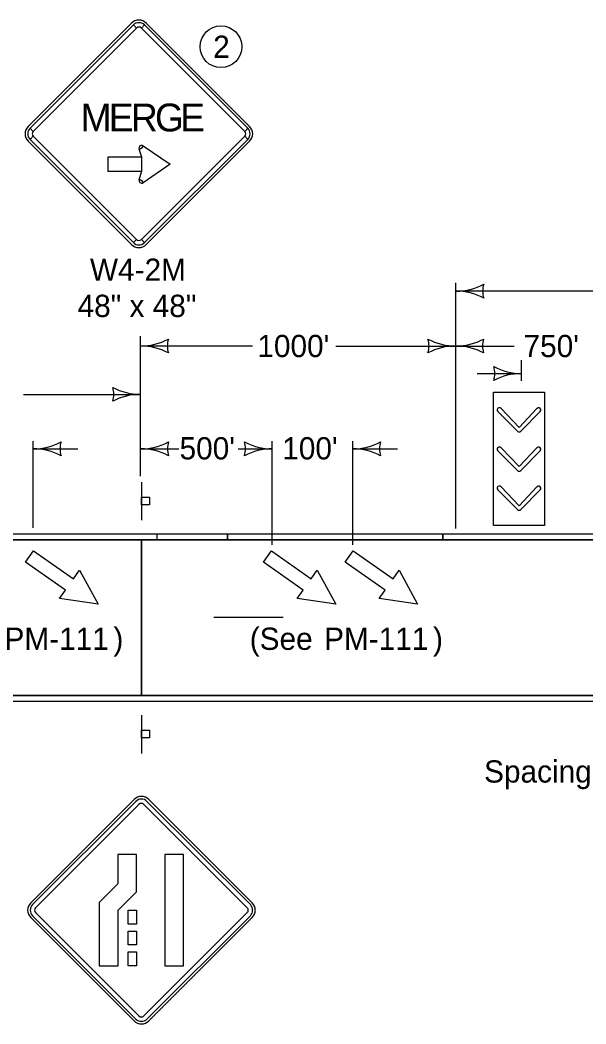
# Model space of a CAD drawing. Extents: x 10134 to 13311, y 7934 to 9733.
# Drawn here: x 10902 to 11309, y 9011 to 9733 of the extents above; entities that cross this region are included whole.
import ezdxf

# ---------------------------------------------------------------- set-up
doc = ezdxf.new("R2010")
doc.units = 0
for name, color, linetype in [('dsnCellElements', 7, 'Continuous'), ('dsnstdModifiedBlock', 7, 'Continuous'), ('dsnStdNote', 7, 'Continuous'), ('dsnStdShading', 7, 'Continuous'), ('SheetText', 7, 'Continuous')]:
    doc.layers.add(name, color=color, linetype=linetype)

msp = doc.modelspace()

# ---------------------------------------------------------------- linework, layer by layer
at = {"layer": 'dsnCellElements'}
for p, q in [((10982.3, 9730.38), (10908.06, 9656.13)), ((10983.63, 9729.05), (10985.84, 9726.84)), ((10989.37, 9726.84), (10991.58, 9729.05)), ((11067.15, 9656.13), (10992.91, 9730.38)), ((10911.59, 9652.59), (10909.38, 9654.8)), ((11065.83, 9654.8), (11063.62, 9652.59)), ((10909.38, 9646.85), (10911.59, 9649.06)), ((11063.62, 9649.06), (11065.83, 9646.85)), ((10908.06, 9645.52), (10982.3, 9571.28)), ((10989.64, 9640.51), (10987.71, 9639.87)), ((10990.72, 9642.23), (10989.64, 9640.51)), ((10992.91, 9571.28), (11067.15, 9645.52)), ((10987.71, 9618.04), (10989.64, 9617.39)), ((10989.64, 9617.39), (10990.72, 9615.67)), ((10985.84, 9574.81), (10983.63, 9572.6)), ((10991.58, 9572.6), (10989.37, 9574.81)), ((11261.86, 9437.05), (11275.95, 9451.15)), ((11261.86, 9408.82), (11275.95, 9422.91)), ((11261.86, 9380.75), (11275.95, 9394.85)), ((10989.42, 9233.04), (10989.42, 9205.54)), ((10909.87, 9098.12), (10984.12, 9172.37)), ((10984.12, 9172.37), (10909.87, 9098.12)), ((10911.2, 9096.8), (10985.44, 9171.04)), ((10984.12, 9172.37), (10984.12, 9172.37)), ((10993.4, 9171.04), (11067.65, 9096.8)), ((10994.73, 9172.37), (11068.97, 9098.12)), ((11068.97, 9098.12), (10994.73, 9172.37)), ((10987.65, 9168.83), (10913.41, 9094.59)), ((10987.65, 9168.83), (10987.65, 9168.84)), ((11065.44, 9094.59), (10991.19, 9168.83)), ((10913.41, 9091.05), (10987.65, 9016.81)), ((10991.19, 9016.81), (11065.44, 9091.05)), ((10984.12, 9013.27), (10909.87, 9087.52)), ((10909.87, 9087.52), (10984.12, 9013.27)), ((10985.44, 9014.6), (10911.2, 9088.84)), ((11067.65, 9088.84), (10993.4, 9014.6)), ((11068.97, 9087.52), (10994.73, 9013.27)), ((10994.73, 9013.27), (11068.97, 9087.52))]:
    msp.add_line(p, q, dxfattribs=at)
for points in [[(10983.63, 9729.05), (10909.38, 9654.8), (10911.59, 9652.59), (10985.84, 9726.84), (10983.63, 9729.05)], [(11065.83, 9654.8), (10991.58, 9729.05), (10989.37, 9726.84), (11063.62, 9652.59), (11065.83, 9654.8)], [(10909.38, 9646.85), (10983.63, 9572.6), (10985.84, 9574.81), (10911.59, 9649.06), (10909.38, 9646.85)], [(10991.58, 9572.6), (11065.83, 9646.85), (11063.62, 9649.06), (10989.37, 9574.81), (10991.58, 9572.6)], [(11009.95, 9628.95), (10990.72, 9615.67), (10989.64, 9617.39), (10987.71, 9618.04), (10989.7, 9623.95), (10989.7, 9633.95), (10987.71, 9639.87), (10989.64, 9640.51), (10990.72, 9642.23), (11009.95, 9628.95)], [(10965.26, 9633.95), (10965.26, 9623.95), (10989.7, 9623.95), (10989.7, 9633.95), (10965.26, 9633.95)], [(11279.03, 9465.2), (11279.03, 9369.2), (11242.32, 9369.2), (11242.32, 9465.2)], [(10989.52, 9216.59), (10989.52, 9222.22), (10995.14, 9222.22), (10995.14, 9216.59)], [(10972.42, 9111.67), (10959.17, 9098.41), (10959.17, 9052.82), (10972.67, 9052.82), (10972.67, 9092.82), (10985.92, 9106.07), (10985.92, 9132.82), (10972.42, 9132.82)], [(11006.17, 9132.82), (11006.17, 9052.82), (11019.67, 9052.82), (11019.67, 9132.82)], [(10979.92, 9092.82), (10985.92, 9092.82), (10985.92, 9082.82), (10979.92, 9082.82)], [(10979.92, 9077.82), (10985.92, 9077.82), (10985.92, 9067.82), (10979.92, 9067.82)], [(10979.92, 9062.82), (10985.92, 9062.82), (10985.92, 9052.82), (10979.92, 9052.82)]]:
    msp.add_lwpolyline(points, close=True, dxfattribs=at)
for points in [[(11273.63, 9453.48), (11273.57, 9453.42), (11260.67, 9439.85), (11247.77, 9453.43)], [(11245.37, 9451.18), (11245.42, 9451.13), (11259.5, 9437.04), (11259.52, 9437.03)], [(11245.37, 9422.94), (11245.42, 9422.89), (11259.5, 9408.81), (11259.52, 9408.79)], [(11273.63, 9425.25), (11273.57, 9425.18), (11260.67, 9411.61), (11247.77, 9425.2)], [(11245.37, 9394.88), (11245.42, 9394.83), (11259.5, 9380.74), (11259.52, 9380.73)], [(11273.63, 9397.19), (11273.57, 9397.12), (11260.67, 9383.55), (11247.77, 9397.13)], [(10985.44, 9171.04), (10911.2, 9096.8)], [(11067.65, 9096.8), (10993.4, 9171.04)], [(10987.65, 9168.84), (10913.41, 9094.59)], [(11065.44, 9094.59), (10991.19, 9168.84)], [(10913.41, 9091.05), (10987.65, 9016.81)], [(10991.19, 9016.81), (11065.44, 9091.05)], [(10911.2, 9088.84), (10985.44, 9014.6)], [(10993.4, 9014.6), (11067.65, 9088.84)]]:
    msp.add_lwpolyline(points, dxfattribs=at)
for centre, radius, start, end in [((10987.61, 9725.07), 7.5, 44.99999, 134.99974), ((10987.61, 9725.07), 5.62, 44.99999, 134.99974), ((10987.61, 9725.07), 2.5, 44.99999, 134.99974), ((10913.36, 9650.83), 7.5, 134.99974, 224.99995), ((10913.36, 9650.83), 5.62, 134.99974, 224.99995), ((11061.85, 9650.83), 5.62, 315.00016, 44.9998), ((11061.85, 9650.83), 7.5, 315.00016, 44.9998), ((10913.36, 9650.83), 2.5, 134.99974, 224.99995), ((11061.85, 9650.83), 2.5, 315.00016, 44.9998), ((10989.64, 9640.51), 2.03, 57.68757, 198.58133), ((10989.64, 9617.39), 2.03, 161.41814, 302.31247), ((10987.61, 9576.58), 2.5, 224.99995, 315.00016), ((10987.61, 9576.58), 7.5, 224.99995, 315.00016), ((10987.61, 9576.58), 5.62, 224.99995, 315.00016), ((11246.56, 9452.32), 1.65, 42.63982, 223.799), ((11274.79, 9452.32), 1.65, 314.71897, 134.90254), ((11260.67, 9438.2), 1.65, 225.39017, 315.83844), ((11246.56, 9424.08), 1.65, 42.63982, 223.799), ((11274.79, 9424.08), 1.65, 314.71897, 134.90254), ((11260.67, 9409.97), 1.65, 225.39017, 315.83844), ((11246.56, 9396.02), 1.65, 42.63982, 223.799), ((11274.79, 9396.02), 1.65, 314.71897, 134.90254), ((11260.67, 9381.9), 1.65, 225.39017, 315.83844), ((10989.42, 9167.07), 7.5, 45.00026, 135.00001), ((10989.42, 9167.07), 7.5, 45.00026, 135.00001), ((10989.42, 9167.07), 5.63, 45.00026, 135.00001), ((10989.42, 9167.07), 5.63, 45.00026, 135.00001), ((10989.42, 9167.07), 2.5, 45.00026, 135.00001), ((10989.42, 9167.07), 2.5, 45.00026, 135.00001), ((10915.18, 9092.82), 7.5, 135.0002, 224.99984), ((10915.18, 9092.82), 7.5, 135.0002, 224.99984), ((11063.67, 9092.82), 7.5, 315.00005, 45.00026), ((11063.67, 9092.82), 7.5, 315.00005, 45.00026), ((10915.18, 9092.82), 5.63, 135.0002, 224.99984), ((10915.18, 9092.82), 5.63, 135.0002, 224.99984), ((10915.18, 9092.82), 2.5, 135.0002, 224.99984), ((10915.18, 9092.82), 2.5, 135.0002, 224.99984), ((11063.67, 9092.82), 2.5, 315.00005, 45.00026), ((11063.67, 9092.82), 2.5, 315.00005, 45.00026), ((11063.67, 9092.82), 5.63, 315.00005, 45.00026), ((11063.67, 9092.82), 5.63, 315.00005, 45.00026), ((10989.42, 9018.57), 7.5, 224.99984, 315.00005), ((10989.42, 9018.57), 7.5, 224.99984, 315.00005), ((10989.42, 9018.57), 5.63, 224.99984, 315.00005), ((10989.42, 9018.57), 5.63, 224.99984, 315.00005), ((10989.42, 9018.57), 2.5, 224.99984, 315.00005), ((10989.42, 9018.57), 2.5, 224.99984, 315.00005)]:
    msp.add_arc(centre, radius, start, end, dxfattribs=at)
at = {"layer": 'dsnstdModifiedBlock'}
for p, q in [((10162.64, 9359.04), (11358.88, 9359.04)), ((10906.21, 9342.96), (10911.95, 9351.16)), ((10911.95, 9351.16), (10940.61, 9331.09)), ((11077.02, 9342.96), (11082.76, 9351.16)), ((11082.76, 9351.16), (11111.42, 9331.09)), ((11135.79, 9342.96), (11141.53, 9351.16)), ((11141.53, 9351.16), (11170.19, 9331.09)), ((10934.88, 9322.89), (10906.21, 9342.96)), ((10940.61, 9331.09), (10944.91, 9337.23)), ((10944.91, 9337.23), (10958.22, 9312.65)), ((11105.68, 9322.89), (11077.02, 9342.96)), ((11111.42, 9331.09), (11115.72, 9337.23)), ((11115.72, 9337.23), (11129.03, 9312.65)), ((11164.45, 9322.89), (11135.79, 9342.96)), ((11170.19, 9331.09), (11174.49, 9337.23)), ((11174.49, 9337.23), (11187.8, 9312.65)), ((10930.57, 9316.75), (10934.88, 9322.89)), ((11101.38, 9316.75), (11105.68, 9322.89)), ((11160.15, 9316.75), (11164.45, 9322.89)), ((10958.22, 9312.65), (10930.57, 9316.75)), ((11129.03, 9312.65), (11101.38, 9316.75)), ((11187.8, 9312.65), (11160.15, 9316.75)), ((10154.68, 9247.02), (11772.83, 9247.02))]:
    msp.add_line(p, q, dxfattribs=at)
msp.add_lwpolyline([(11041.36, 9303.44), (11091.35, 9303.44)], dxfattribs=at)
at = {"layer": 'dsnStdNote'}
msp.add_circle((11046.57, 9713.4), 15, dxfattribs=at)
at = {"layer": 'dsnStdShading'}
for p, q in [((11083.44, 9363.04), (10891.48, 9363.04)), ((10891.48, 9359.04), (11083.44, 9359.04)), ((10989.42, 9247.04), (10989.42, 9359.04)), ((11051.29, 9359.04), (10989.42, 9359.04)), ((10989.42, 9359.04), (10989.42, 9247.04)), ((11051.29, 9363.04), (11000.47, 9363.04)), ((11000.47, 9363.04), (11000.47, 9359.04)), ((11000.47, 9359.04), (11051.29, 9359.04)), ((11205.92, 9363.04), (11051.29, 9363.04)), ((11051.29, 9363.04), (11051.29, 9359.04)), ((11051.29, 9359.04), (11051.29, 9363.04)), ((11051.29, 9359.04), (11205.92, 9359.04)), ((11205.92, 9359.04), (11051.29, 9359.04)), ((11083.44, 9359.04), (11083.44, 9363.04)), ((11205.92, 9359.04), (11205.92, 9363.04)), ((12420.28, 9363.04), (11205.92, 9363.04)), ((11205.92, 9363.04), (11205.92, 9359.04)), ((11417.27, 9359.04), (11205.92, 9359.04)), ((11205.92, 9359.04), (11417.27, 9359.04)), ((11538.19, 9247.04), (10154.66, 9247.04)), ((10154.66, 9247.04), (10989.42, 9247.04)), ((10158.66, 9243.04), (11564.95, 9243.04)), ((10158.66, 9243.04), (11536.47, 9243.04)), ((10989.42, 9247.04), (11538.19, 9247.04))]:
    msp.add_line(p, q, dxfattribs=at)
msp.add_lwpolyline([(10989.42, 9359.04), (10891.48, 9359.04), (10840.66, 9359.04)], dxfattribs=at)
msp.add_lwpolyline([(11051.29, 9359.04), (11205.92, 9359.04), (11205.92, 9363.04), (11051.29, 9363.04)], close=True, dxfattribs=at)
at = {"layer": 'SheetText'}
for p, q in [((11215.26, 9367.17), (11215.26, 9543.8)), ((11692.25, 9537.75), (11215.32, 9537.75)), ((10988.76, 9404.81), (10988.76, 9505.45)), ((11069.26, 9498.32), (10988.76, 9498.32)), ((11129.06, 9498.32), (11215.26, 9498.32)), ((11215.26, 9498.32), (11257.23, 9498.32)), ((11262.56, 9473.2), (11262.56, 9488.06)), ((11230.56, 9478.51), (11262.56, 9478.51)), ((10904.79, 9463.58), (10988.76, 9463.58)), ((10911.69, 9367.57), (10911.69, 9430.02)), ((11083.44, 9355.42), (11083.44, 9430.02)), ((11141.27, 9355.42), (11141.27, 9430.02)), ((10911.69, 9424.43), (10943.69, 9424.43)), ((10989.58, 9424.43), (11016.19, 9424.43)), ((11058.94, 9424.43), (11083.44, 9424.43)), ((11141.27, 9424.43), (11173.27, 9424.43)), ((10989.42, 9400.54), (10989.42, 9373.04))]:
    msp.add_line(p, q, dxfattribs=at)
msp.add_lwpolyline([(10989.52, 9384.09), (10989.52, 9389.72), (10995.14, 9389.72), (10995.14, 9384.09)], close=True, dxfattribs=at)
for centre, radius, start, end in [((11215.32, 9580.25), 42.5, 270, 298.07249), ((11250.95, 9537.75), 16.42, 162.26665, 197.73335), ((11215.32, 9495.25), 42.5, 61.92751, 90), ((10988.76, 9540.82), 42.5, 270, 298.07249), ((11024.4, 9498.32), 16.42, 162.26665, 197.73335), ((11179.62, 9498.32), 16.42, 342.26665, 17.73335), ((11215.26, 9540.82), 42.5, 241.92751, 270), ((11215.26, 9540.82), 42.5, 270, 298.07249), ((11250.89, 9498.32), 16.42, 162.26665, 197.73335), ((10988.76, 9455.82), 42.5, 61.92751, 90), ((11215.26, 9455.82), 42.5, 90, 118.07249), ((11215.26, 9455.82), 42.5, 61.92751, 90), ((11226.92, 9478.51), 16.42, 342.26665, 17.73335), ((11262.56, 9521.01), 42.5, 241.92751, 270), ((11262.56, 9436.01), 42.5, 90, 118.07249), ((10953.13, 9463.58), 16.42, 342.26665, 17.73335), ((10988.76, 9506.08), 42.5, 241.92751, 270), ((10988.76, 9421.08), 42.5, 90, 118.07249), ((10911.69, 9466.93), 42.5, 270, 298.07249), ((10911.69, 9381.93), 42.5, 61.92751, 90), ((10947.32, 9424.43), 16.42, 162.26665, 197.73335), ((10988.98, 9466.93), 42.5, 270, 298.07249), ((10988.98, 9381.93), 42.5, 61.92751, 90), ((11024.61, 9424.43), 16.42, 162.26665, 197.73335), ((11047.81, 9424.43), 16.42, 342.26665, 17.73335), ((11083.44, 9466.93), 42.5, 241.92751, 270), ((11083.44, 9381.93), 42.5, 90, 118.07249), ((11141.27, 9466.93), 42.5, 270, 298.07249), ((11141.27, 9381.93), 42.5, 61.92751, 90), ((11176.9, 9424.43), 16.42, 162.26665, 197.73335)]:
    msp.add_arc(centre, radius, start, end, dxfattribs=at)

# ---------------------------------------------------------------- texts
at = {"layer": 'dsnCellElements'}
for s, p in [('M', (10945.72, 9652.55)), ('E', (10965.93, 9652.55)), ('R', (10981.9, 9652.55)), ('G', (10999.13, 9652.55)), ('E', (11017.3, 9652.55))]:
    msp.add_text(s, height=20, dxfattribs=at).set_placement(p)
at = {"layer": 'dsnStdNote'}
msp.add_text('2', height=16, dxfattribs=at).set_placement((11040.95, 9705.4))
at = {"layer": 'SheetText'}
for s, p in [('W4-2M', (10952.44, 9545.16)), ('48" x 48"', (10943.54, 9519.16)), ("1000'", (11072.7, 9490.32)), ("750'", (11263.92, 9490.32)), ("500'", (11016.81, 9416.8)), ("100'", (11090.58, 9416.8)), ('PM-111', (10891.06, 9279.91)), (')', (10969.31, 9279.91)), ('(See ', (11067.22, 9279.91)), ('PM-111', (11120.64, 9279.91)), (')', (11198.89, 9279.91)), ("Spacing = 65'", (11235.58, 9184.53))]:
    msp.add_text(s, height=16, dxfattribs=at).set_placement(p)

doc.saveas('drawing.dxf')
